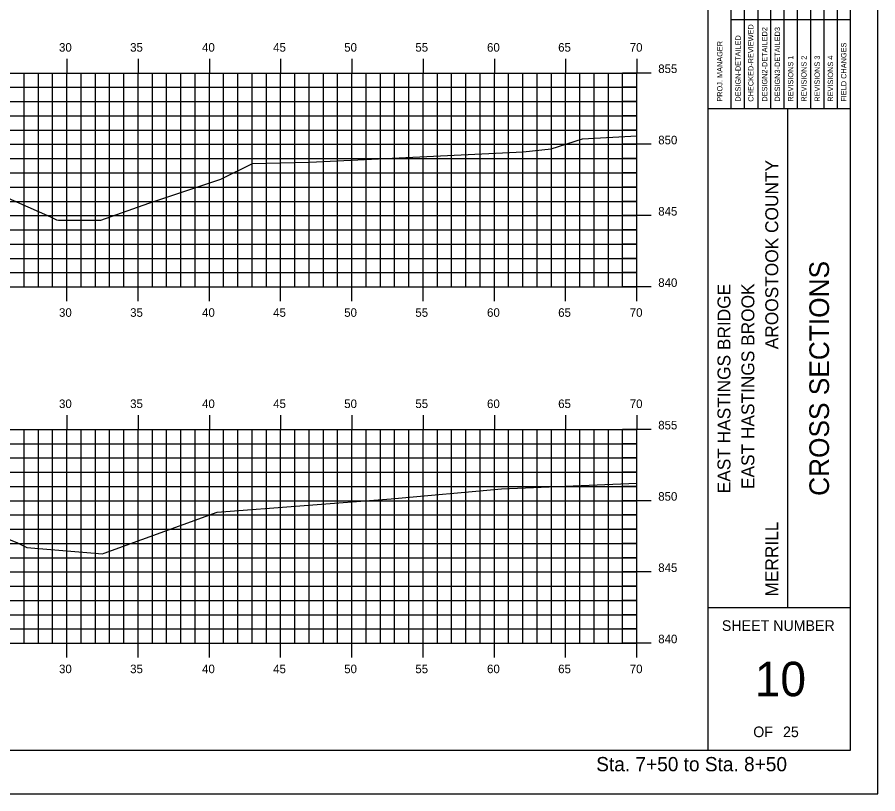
# Model space of a CAD drawing. Extents: x 2194256 to 2194747, y 863888 to 863998.
# Drawn here: x 2194503.3 to 2194563.6, y 863888.4 to 863942.9 of the extents above; entities that cross this region are included whole.
import ezdxf

# ---------------------------------------------------------------- set-up
doc = ezdxf.new("R2010")
doc.units = 0
for name, color, linetype in [('BORDER', 7, 'Continuous'), ('BRIDGE_TITLE', 7, 'Continuous'), ('H_V ANNOTATION', 7, 'Continuous'), ('MAJOR', 7, 'Continuous'), ('MINOR', 7, 'Continuous'), ('PLOT BOUNDARY', 7, 'Continuous'), ('S_Roadway_Centerline', 7, 'Continuous')]:
    doc.layers.add(name, color=color, linetype=linetype)

msp = doc.modelspace()

# ---------------------------------------------------------------- linework, layer by layer
at = {"layer": 'BORDER'}
for p, q in [((2194551.743, 863891.446), (2194551.743, 863996.446)), ((2194551.743, 863936.449), (2194561.743, 863936.449)), ((2194557.334, 863901.449), (2194557.334, 863936.449)), ((2194551.743, 863901.449), (2194561.743, 863901.449))]:
    msp.add_line(p, q, dxfattribs=at)
msp.add_lwpolyline([(2194401.743, 863891.446), (2194561.743, 863891.446), (2194561.743, 863996.446), (2194401.743, 863996.446)], close=True, dxfattribs=at)
for points in [[(2194554.29, 863936.452), (2194554.29, 863953.949)], [(2194555.222, 863953.949), (2194555.222, 863936.452)], [(2194556.154, 863936.452), (2194556.154, 863953.949)], [(2194557.085, 863936.452), (2194557.085, 863953.949)], [(2194558.017, 863936.452), (2194558.017, 863953.949)], [(2194558.949, 863936.452), (2194558.949, 863953.949)], [(2194559.881, 863936.452), (2194559.881, 863953.949)], [(2194560.812, 863936.452), (2194560.812, 863953.949)], [(2194553.359, 863936.452), (2194553.359, 863953.243)], [(2194553.358, 863942.699), (2194561.743, 863942.699)]]:
    msp.add_lwpolyline(points, dxfattribs=at)
at = {"layer": 'MAJOR'}
for p, q in [((2194506.743, 863939.948), (2194506.743, 863938.946)), ((2194511.743, 863939.948), (2194511.743, 863938.946)), ((2194516.743, 863939.948), (2194516.743, 863938.946)), ((2194521.743, 863939.948), (2194521.743, 863938.946)), ((2194526.743, 863939.948), (2194526.743, 863938.946)), ((2194531.743, 863939.948), (2194531.743, 863938.946)), ((2194536.743, 863939.948), (2194536.743, 863938.946)), ((2194541.743, 863939.948), (2194541.743, 863938.946)), ((2194546.743, 863939.948), (2194546.743, 863938.946)), ((2194406.743, 863938.946), (2194546.743, 863938.946)), ((2194506.743, 863923.946), (2194506.743, 863938.946)), ((2194511.743, 863923.946), (2194511.743, 863938.946)), ((2194516.743, 863923.946), (2194516.743, 863938.946)), ((2194521.743, 863923.946), (2194521.743, 863938.946)), ((2194526.743, 863923.946), (2194526.743, 863938.946)), ((2194531.743, 863923.946), (2194531.743, 863938.946)), ((2194536.743, 863923.946), (2194536.743, 863938.946)), ((2194541.743, 863923.946), (2194541.743, 863938.946)), ((2194547.745, 863938.946), (2194545.741, 863938.946)), ((2194546.743, 863923.946), (2194546.743, 863938.946)), ((2194546.743, 863923.946), (2194546.743, 863938.946)), ((2194406.743, 863933.946), (2194546.743, 863933.946)), ((2194547.745, 863933.946), (2194545.741, 863933.946)), ((2194406.743, 863928.946), (2194546.743, 863928.946)), ((2194547.745, 863928.946), (2194545.741, 863928.946)), ((2194406.743, 863923.946), (2194546.743, 863923.946)), ((2194506.743, 863922.944), (2194506.743, 863923.946)), ((2194511.743, 863922.944), (2194511.743, 863923.946)), ((2194516.743, 863922.944), (2194516.743, 863923.946)), ((2194521.743, 863922.944), (2194521.743, 863923.946)), ((2194526.743, 863922.944), (2194526.743, 863923.946)), ((2194531.743, 863922.944), (2194531.743, 863923.946)), ((2194536.743, 863922.944), (2194536.743, 863923.946)), ((2194541.743, 863922.944), (2194541.743, 863923.946)), ((2194547.745, 863923.946), (2194545.741, 863923.946)), ((2194546.743, 863922.944), (2194546.743, 863923.946)), ((2194506.743, 863914.948), (2194506.743, 863913.946)), ((2194511.743, 863914.948), (2194511.743, 863913.946)), ((2194516.743, 863914.948), (2194516.743, 863913.946)), ((2194521.743, 863914.948), (2194521.743, 863913.946)), ((2194526.743, 863914.948), (2194526.743, 863913.946)), ((2194531.743, 863914.948), (2194531.743, 863913.946)), ((2194536.743, 863914.948), (2194536.743, 863913.946)), ((2194541.743, 863914.948), (2194541.743, 863913.946)), ((2194546.743, 863914.948), (2194546.743, 863913.946)), ((2194406.743, 863913.946), (2194546.743, 863913.946)), ((2194506.743, 863898.946), (2194506.743, 863913.946)), ((2194511.743, 863898.946), (2194511.743, 863913.946)), ((2194516.743, 863898.946), (2194516.743, 863913.946)), ((2194521.743, 863898.946), (2194521.743, 863913.946)), ((2194526.743, 863898.946), (2194526.743, 863913.946)), ((2194531.743, 863898.946), (2194531.743, 863913.946)), ((2194536.743, 863898.946), (2194536.743, 863913.946)), ((2194541.743, 863898.946), (2194541.743, 863913.946)), ((2194547.745, 863913.946), (2194545.741, 863913.946)), ((2194546.743, 863898.946), (2194546.743, 863913.946)), ((2194546.743, 863898.946), (2194546.743, 863913.946)), ((2194406.743, 863908.946), (2194546.743, 863908.946)), ((2194547.745, 863908.946), (2194545.741, 863908.946)), ((2194406.743, 863903.946), (2194546.743, 863903.946)), ((2194547.745, 863903.946), (2194545.741, 863903.946)), ((2194406.743, 863898.946), (2194546.743, 863898.946)), ((2194506.743, 863897.944), (2194506.743, 863898.946)), ((2194511.743, 863897.944), (2194511.743, 863898.946)), ((2194516.743, 863897.944), (2194516.743, 863898.946)), ((2194521.743, 863897.944), (2194521.743, 863898.946)), ((2194526.743, 863897.944), (2194526.743, 863898.946)), ((2194531.743, 863897.944), (2194531.743, 863898.946)), ((2194536.743, 863897.944), (2194536.743, 863898.946)), ((2194541.743, 863897.944), (2194541.743, 863898.946)), ((2194547.745, 863898.946), (2194545.741, 863898.946)), ((2194546.743, 863897.944), (2194546.743, 863898.946))]:
    msp.add_line(p, q, dxfattribs=at)
at = {"layer": 'MINOR'}
for p, q in [((2194503.743, 863923.946), (2194503.743, 863938.946)), ((2194504.743, 863923.946), (2194504.743, 863938.946)), ((2194505.743, 863923.946), (2194505.743, 863938.946)), ((2194507.743, 863923.946), (2194507.743, 863938.946)), ((2194508.743, 863923.946), (2194508.743, 863938.946)), ((2194509.743, 863923.946), (2194509.743, 863938.946)), ((2194510.743, 863923.946), (2194510.743, 863938.946)), ((2194512.743, 863923.946), (2194512.743, 863938.946)), ((2194513.743, 863923.946), (2194513.743, 863938.946)), ((2194514.743, 863923.946), (2194514.743, 863938.946)), ((2194515.743, 863923.946), (2194515.743, 863938.946)), ((2194517.743, 863923.946), (2194517.743, 863938.946)), ((2194518.743, 863923.946), (2194518.743, 863938.946)), ((2194519.743, 863923.946), (2194519.743, 863938.946)), ((2194520.743, 863923.946), (2194520.743, 863938.946)), ((2194522.743, 863923.946), (2194522.743, 863938.946)), ((2194523.743, 863923.946), (2194523.743, 863938.946)), ((2194524.743, 863923.946), (2194524.743, 863938.946)), ((2194525.743, 863923.946), (2194525.743, 863938.946)), ((2194527.743, 863923.946), (2194527.743, 863938.946)), ((2194528.743, 863923.946), (2194528.743, 863938.946)), ((2194529.743, 863923.946), (2194529.743, 863938.946)), ((2194530.743, 863923.946), (2194530.743, 863938.946)), ((2194532.743, 863923.946), (2194532.743, 863938.946)), ((2194533.743, 863923.946), (2194533.743, 863938.946)), ((2194534.743, 863923.946), (2194534.743, 863938.946)), ((2194535.743, 863923.946), (2194535.743, 863938.946)), ((2194537.743, 863923.946), (2194537.743, 863938.946)), ((2194538.743, 863923.946), (2194538.743, 863938.946)), ((2194539.743, 863923.946), (2194539.743, 863938.946)), ((2194540.743, 863923.946), (2194540.743, 863938.946)), ((2194542.743, 863923.946), (2194542.743, 863938.946)), ((2194543.743, 863923.946), (2194543.743, 863938.946)), ((2194544.743, 863923.946), (2194544.743, 863938.946)), ((2194545.743, 863923.946), (2194545.743, 863938.946)), ((2194406.743, 863937.946), (2194546.743, 863937.946)), ((2194546.743, 863937.946), (2194545.741, 863937.946)), ((2194406.743, 863936.946), (2194546.743, 863936.946)), ((2194546.743, 863936.946), (2194545.741, 863936.946)), ((2194406.743, 863935.946), (2194546.743, 863935.946)), ((2194546.743, 863935.946), (2194545.741, 863935.946)), ((2194406.743, 863934.946), (2194546.743, 863934.946)), ((2194546.743, 863934.946), (2194545.741, 863934.946)), ((2194406.743, 863932.946), (2194546.743, 863932.946)), ((2194546.743, 863932.946), (2194545.741, 863932.946)), ((2194406.743, 863931.946), (2194546.743, 863931.946)), ((2194546.743, 863931.946), (2194545.741, 863931.946)), ((2194406.743, 863930.946), (2194546.743, 863930.946)), ((2194546.743, 863930.946), (2194545.741, 863930.946)), ((2194406.743, 863929.946), (2194546.743, 863929.946)), ((2194546.743, 863929.946), (2194545.741, 863929.946)), ((2194406.743, 863927.946), (2194546.743, 863927.946)), ((2194546.743, 863927.946), (2194545.741, 863927.946)), ((2194406.743, 863926.946), (2194546.743, 863926.946)), ((2194546.743, 863926.946), (2194545.741, 863926.946)), ((2194406.743, 863925.946), (2194546.743, 863925.946)), ((2194546.743, 863925.946), (2194545.741, 863925.946)), ((2194406.743, 863924.946), (2194546.743, 863924.946)), ((2194546.743, 863924.946), (2194545.741, 863924.946)), ((2194503.743, 863898.946), (2194503.743, 863913.946)), ((2194504.743, 863898.946), (2194504.743, 863913.946)), ((2194505.743, 863898.946), (2194505.743, 863913.946)), ((2194507.743, 863898.946), (2194507.743, 863913.946)), ((2194508.743, 863898.946), (2194508.743, 863913.946)), ((2194509.743, 863898.946), (2194509.743, 863913.946)), ((2194510.743, 863898.946), (2194510.743, 863913.946)), ((2194512.743, 863898.946), (2194512.743, 863913.946)), ((2194513.743, 863898.946), (2194513.743, 863913.946)), ((2194514.743, 863898.946), (2194514.743, 863913.946)), ((2194515.743, 863898.946), (2194515.743, 863913.946)), ((2194517.743, 863898.946), (2194517.743, 863913.946)), ((2194518.743, 863898.946), (2194518.743, 863913.946)), ((2194519.743, 863898.946), (2194519.743, 863913.946)), ((2194520.743, 863898.946), (2194520.743, 863913.946)), ((2194522.743, 863898.946), (2194522.743, 863913.946)), ((2194523.743, 863898.946), (2194523.743, 863913.946)), ((2194524.743, 863898.946), (2194524.743, 863913.946)), ((2194525.743, 863898.946), (2194525.743, 863913.946)), ((2194527.743, 863898.946), (2194527.743, 863913.946)), ((2194528.743, 863898.946), (2194528.743, 863913.946)), ((2194529.743, 863898.946), (2194529.743, 863913.946)), ((2194530.743, 863898.946), (2194530.743, 863913.946)), ((2194532.743, 863898.946), (2194532.743, 863913.946)), ((2194533.743, 863898.946), (2194533.743, 863913.946)), ((2194534.743, 863898.946), (2194534.743, 863913.946)), ((2194535.743, 863898.946), (2194535.743, 863913.946)), ((2194537.743, 863898.946), (2194537.743, 863913.946)), ((2194538.743, 863898.946), (2194538.743, 863913.946)), ((2194539.743, 863898.946), (2194539.743, 863913.946)), ((2194540.743, 863898.946), (2194540.743, 863913.946)), ((2194542.743, 863898.946), (2194542.743, 863913.946)), ((2194543.743, 863898.946), (2194543.743, 863913.946)), ((2194544.743, 863898.946), (2194544.743, 863913.946)), ((2194545.743, 863898.946), (2194545.743, 863913.946)), ((2194406.743, 863912.946), (2194546.743, 863912.946)), ((2194546.743, 863912.946), (2194545.741, 863912.946)), ((2194406.743, 863911.946), (2194546.743, 863911.946)), ((2194546.743, 863911.946), (2194545.741, 863911.946)), ((2194406.743, 863910.946), (2194546.743, 863910.946)), ((2194546.743, 863910.946), (2194545.741, 863910.946)), ((2194406.743, 863909.946), (2194546.743, 863909.946)), ((2194546.743, 863909.946), (2194545.741, 863909.946)), ((2194406.743, 863907.946), (2194546.743, 863907.946)), ((2194546.743, 863907.946), (2194545.741, 863907.946)), ((2194406.743, 863906.946), (2194546.743, 863906.946)), ((2194546.743, 863906.946), (2194545.741, 863906.946)), ((2194406.743, 863905.946), (2194546.743, 863905.946)), ((2194546.743, 863905.946), (2194545.741, 863905.946)), ((2194406.743, 863904.946), (2194546.743, 863904.946)), ((2194546.743, 863904.946), (2194545.741, 863904.946)), ((2194406.743, 863902.946), (2194546.743, 863902.946)), ((2194546.743, 863902.946), (2194545.741, 863902.946)), ((2194406.743, 863901.946), (2194546.743, 863901.946)), ((2194546.743, 863901.946), (2194545.741, 863901.946)), ((2194406.743, 863900.946), (2194546.743, 863900.946)), ((2194546.743, 863900.946), (2194545.741, 863900.946)), ((2194406.743, 863899.946), (2194546.743, 863899.946)), ((2194546.743, 863899.946), (2194545.741, 863899.946))]:
    msp.add_line(p, q, dxfattribs=at)
at = {"layer": 'PLOT BOUNDARY'}
msp.add_lwpolyline([(2194393.65, 863888.387), (2194563.65, 863888.387), (2194563.65, 863998.387), (2194393.65, 863998.387)], close=True, dxfattribs=at)
at = {"layer": 'S_Roadway_Centerline'}
for points in [[(2194500.582, 863931.046), (2194505.6, 863928.851), (2194506.015, 863928.642), (2194506.161, 863928.63), (2194509.129, 863928.62), (2194512.493, 863929.813), (2194517.556, 863931.504), (2194519.773, 863932.592), (2194523.766, 863932.692), (2194538.754, 863933.43), (2194540.724, 863933.634), (2194542.919, 863934.322), (2194546.743, 863934.545)], [(2194498.817, 863907.801), (2194503.284, 863905.992), (2194503.943, 863905.66), (2194508.416, 863905.3), (2194509.235, 863905.22), (2194509.367, 863905.265), (2194517.299, 863908.15), (2194529.509, 863909.082), (2194537.252, 863909.768), (2194546.743, 863910.177)]]:
    msp.add_lwpolyline(points, dxfattribs=at)

# ---------------------------------------------------------------- texts
at = {"layer": 'BORDER'}
for s, height, rotation, p in [('CHECKED-REVIEWED', 0.37275, 90, (2194554.924, 863936.937)), ('DESIGN2-DETAILED2', 0.37275, 90, (2194555.893, 863936.937)), ('DESIGN3-DETAILED3', 0.37275, 90, (2194556.787, 863936.937)), ('DESIGN-DETAILED', 0.37275, 90, (2194554.03, 863936.937)), ('PROJ. MANAGER', 0.37275, 90, (2194552.747, 863936.937)), ('FIELD CHANGES', 0.37275, 90, (2194561.446, 863936.937)), ('REVISIONS 1', 0.37275, 90, (2194557.719, 863936.937)), ('REVISIONS 2', 0.37275, 90, (2194558.651, 863936.937)), ('REVISIONS 3', 0.37275, 90, (2194559.582, 863936.937)), ('REVISIONS 4', 0.37275, 90, (2194560.514, 863936.937)), ('CROSS SECTIONS', 1.37787, 90, (2194560.227, 863909.283)), ('SHEET NUMBER', 0.74527, 360, (2194552.708, 863899.812)), ('10', 2.4194, 360, (2194555.014, 863895.228)), ('OF', 0.7453, 360, (2194554.91, 863892.359)), ('25', 0.7453, 360, (2194556.999, 863892.359))]:
    msp.add_text(s, height=height, rotation=rotation, dxfattribs=at).set_placement(p)
at = {"layer": 'BRIDGE_TITLE'}
for s, height, p in [('AROOSTOOK COUNTY', 0.90716, (2194556.663, 863919.571)), ('EAST HASTINGS BROOK', 0.90716, (2194554.986, 863909.763)), ('EAST HASTINGS BRIDGE', 0.90716, (2194553.309, 863909.466)), ('MERRILL', 0.9072, (2194556.663, 863902.222))]:
    msp.add_text(s, height=height, rotation=90, dxfattribs=at).set_placement(p)
at = {"layer": 'H_V ANNOTATION'}
for s, height, p in [('30', 0.6, (2194506.191, 863940.446)), ('35', 0.6, (2194511.183, 863940.446)), ('40', 0.6, (2194516.229, 863940.446)), ('45', 0.6, (2194521.221, 863940.446)), ('50', 0.6, (2194526.207, 863940.446)), ('55', 0.6, (2194531.199, 863940.446)), ('60', 0.6, (2194536.229, 863940.446)), ('65', 0.6, (2194541.221, 863940.446)), ('70', 0.6, (2194546.245, 863940.446)), ('855', 0.6, (2194548.243, 863938.946)), ('850', 0.6, (2194548.243, 863933.946)), ('845', 0.6, (2194548.243, 863928.946)), ('840', 0.6, (2194548.243, 863923.946)), ('30', 0.6, (2194506.191, 863921.846)), ('35', 0.6, (2194511.183, 863921.846)), ('40', 0.6, (2194516.229, 863921.846)), ('45', 0.6, (2194521.221, 863921.846)), ('50', 0.6, (2194526.207, 863921.846)), ('55', 0.6, (2194531.199, 863921.846)), ('60', 0.6, (2194536.229, 863921.846)), ('65', 0.6, (2194541.221, 863921.846)), ('70', 0.6, (2194546.245, 863921.846)), ('30', 0.6, (2194506.191, 863915.446)), ('35', 0.6, (2194511.183, 863915.446)), ('40', 0.6, (2194516.229, 863915.446)), ('45', 0.6, (2194521.221, 863915.446)), ('50', 0.6, (2194526.207, 863915.446)), ('55', 0.6, (2194531.199, 863915.446)), ('60', 0.6, (2194536.229, 863915.446)), ('65', 0.6, (2194541.221, 863915.446)), ('70', 0.6, (2194546.245, 863915.446)), ('855', 0.6, (2194548.243, 863913.946)), ('850', 0.6, (2194548.243, 863908.946)), ('845', 0.6, (2194548.243, 863903.946)), ('840', 0.6, (2194548.243, 863898.946)), ('30', 0.6, (2194506.191, 863896.846)), ('35', 0.6, (2194511.183, 863896.846)), ('40', 0.6, (2194516.229, 863896.846)), ('45', 0.6, (2194521.221, 863896.846)), ('50', 0.6, (2194526.207, 863896.846)), ('55', 0.6, (2194531.199, 863896.846)), ('60', 0.6, (2194536.229, 863896.846)), ('65', 0.6, (2194541.221, 863896.846)), ('70', 0.6, (2194546.245, 863896.846)), ('Sta. 7+50 to Sta. 8+50', 1.0002, (2194543.892, 863889.966))]:
    msp.add_text(s, height=height, dxfattribs=at).set_placement(p)

doc.saveas('drawing.dxf')
